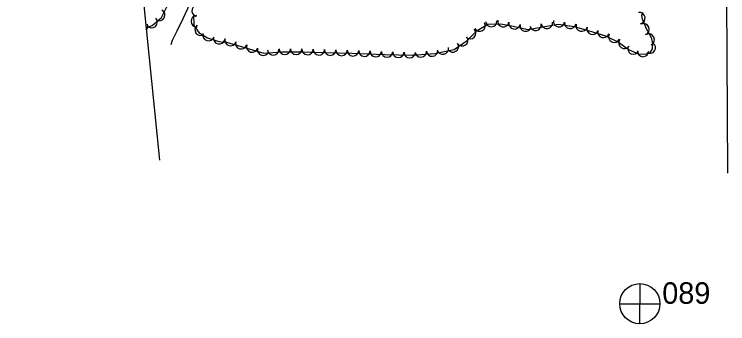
# Model space of a CAD drawing. Extents: x 296487 to 298842, y 31545 to 32791.
# Drawn here: x 297235.4 to 297732.5, y 31644.4 to 31860.3 of the extents above; entities that cross this region are included whole.
import ezdxf

# ---------------------------------------------------------------- set-up
doc = ezdxf.new("R2010")
doc.units = 0
for name, color, linetype in [('Level 11', 7, 'Continuous'), ('Level 17', 7, 'Continuous'), ('Level 18', 7, 'Continuous'), ('Level 4', 7, 'Continuous')]:
    doc.layers.add(name, color=color, linetype=linetype)

msp = doc.modelspace()

# ---------------------------------------------------------------- linework, layer by layer
at = {"layer": 'Level 11'}
msp.add_lwpolyline([(297732.45, 31749.54), (297732.24, 31791.84), (297732.13, 31829.29), (297731.83, 31872.75), (297730.81, 31924.68), (297730.53, 31968.01), (297729.53, 32021.42), (297729.12, 32084.97), (297728.52, 32147.82), (297727.87, 32212.59), (297727.19, 32277.97), (297726.38, 32352.97), (297725.93, 32414.91), (297724.99, 32486.15), (297724.55, 32554.59), (297723.53, 32621.52), (297723.38, 32689.57), (297722.58, 32747.62), (297722.25, 32760.6)], dxfattribs=at)
at = {"layer": 'Level 17'}
msp.add_lwpolyline([(297623.99, 32250.43), (297610.13, 32233.83), (297591.62, 32212.39), (297578.2, 32195.81), (297559.31, 32173.69), (297545.59, 32153.8), (297535.31, 32140.44), (297511.71, 32112.03), (297495.92, 32087.9), (297480.91, 32066.68), (297468.73, 32050.81), (297458.54, 32035.07), (297449.94, 32023.36), (297435.5, 32005.16), (297419.75, 31981.41), (297405.85, 31956.85), (297394.34, 31937.67), (297382.2, 31916.55), (297361.04, 31874.71), (297352.86, 31857.17), (297348.71, 31848.4), (297345.52, 31842.04), (297344.4, 31839.03)], dxfattribs=at)
at = {"layer": 'Level 18'}
for points in [[(297327.25, 31850.84), (297331.54, 31852.45), (297337.95, 31858.15), (297343.21, 31868.17), (297347.46, 31877.57), (297351.9, 31884.76), (297355.88, 31890.53), (297356.1, 31891.33), (297357.16, 31897.95)], [(297360.33, 31860.44), (297360.54, 31852.55), (297364.05, 31847.63), (297369.95, 31843.77), (297377.33, 31841.56), (297381.68, 31840.65)], [(297381.59, 31841.4), (297409.29, 31833.19), (297421.76, 31834.08), (297435.27, 31834.04), (297451.57, 31833.6), (297470.49, 31833.1), (297493.49, 31832.24), (297512.54, 31831.72), (297528.31, 31832.99), (297541.78, 31835.82), (297550.86, 31841.93), (297557.84, 31848.97), (297565.34, 31853.28), (297574.38, 31853.7), (297581.89, 31852.21), (297593.54, 31849.78), (297602.5, 31851.4), (297614.3, 31853.45), (297625.59, 31851.69), (297635.87, 31848.64), (297647.42, 31845.35), (297656.26, 31840.89), (297663.83, 31835.37), (297670.3, 31832.61), (297674.86, 31832.56), (297678.31, 31833.41), (297680.11, 31836.14), (297680.38, 31839.81), (297679.52, 31843.08), (297678.55, 31845.21), (297675.92, 31850.06), (297673.17, 31856.85), (297672.71, 31859.47), (297673.38, 31861.82)]]:
    msp.add_lwpolyline(points, dxfattribs=at)
for centre, radius, start, end in [((297363.15, 31862.68), 4.01, 74.2267, 254.2113), ((297336.41, 31859.7), 4, 242.3173, 62.3019), ((297362.56, 31855.41), 4.01, 91.5031, 271.4877), ((297670.94, 31857.62), 3.96, 279.9695, 99.9541), ((297331.08, 31854.84), 4, 221.6068, 41.5915), ((297559.64, 31852.39), 3.96, 209.8823, 29.867), ((297567.76, 31855.46), 3.96, 182.6945, 2.6792), ((297576.14, 31855.46), 3.96, 168.7931, 348.7777), ((297583.92, 31853.9), 3.96, 168.2529, 348.2376), ((297606.45, 31854.19), 3.96, 189.8481, 9.8328), ((297614.92, 31855.45), 3.96, 171.1845, 351.1691), ((297622.74, 31854.23), 3.96, 171.1845, 351.1691), ((297324.48, 31852.03), 4, 317.0734, 20.6017), ((297365.27, 31849.53), 4.01, 125.5751, 305.5598), ((297553.1, 31847.12), 3.96, 225.2202, 45.2049), ((297591.66, 31852.29), 3.96, 168.2529, 348.2376), ((297598.65, 31852.81), 3.96, 190.2207, 10.2054), ((297630.69, 31852.34), 3.96, 163.4559, 343.4405), ((297638.25, 31850.11), 3.96, 164.0996, 344.0843), ((297673.79, 31849.8), 3.96, 292.0009, 111.9856), ((297370.68, 31845.74), 4.01, 163.292, 343.2767), ((297378.19, 31843.52), 4.01, 168.2661, 348.2508), ((297547.51, 31842.17), 3.96, 213.9344, 33.9191), ((297645.86, 31847.94), 3.96, 164.0996, 344.0843), ((297653.44, 31844.63), 3.96, 153.2639, 333.2486), ((297677.43, 31842.68), 3.96, 294.5386, 114.5233), ((297385.97, 31842.26), 3.96, 163.5052, 343.4899), ((297393.55, 31840.01), 3.96, 163.5052, 343.4899), ((297540.94, 31837.76), 3.96, 213.9344, 33.9191), ((297660.48, 31840.38), 3.96, 143.9214, 323.9061), ((297678.2, 31837), 3.96, 236.5752, 56.5599), ((297401.14, 31837.77), 3.96, 163.5052, 343.4899), ((297408.72, 31835.52), 3.96, 163.5052, 343.4899), ((297415.83, 31835.73), 3.96, 184.0717, 4.0564), ((297423.88, 31836.14), 3.96, 179.838, 359.8227), ((297431.8, 31836.12), 3.96, 179.838, 359.8227), ((297439.75, 31835.99), 3.96, 178.4652, 358.4499), ((297447.66, 31835.77), 3.96, 178.4652, 358.4499), ((297455.57, 31835.57), 3.96, 178.5154, 358.5001), ((297463.48, 31835.36), 3.96, 178.5154, 358.5001), ((297471.41, 31835.14), 3.96, 177.8588, 357.8435), ((297479.31, 31834.85), 3.96, 177.8588, 357.8435), ((297487.22, 31834.55), 3.96, 177.8588, 357.8435), ((297495.11, 31834.27), 3.96, 178.4224, 358.407), ((297518.59, 31834.28), 3.96, 184.6227, 4.6074), ((297526.47, 31834.92), 3.96, 184.6227, 4.6074), ((297533.99, 31836.3), 3.96, 191.889, 11.8737), ((297666.72, 31836.39), 3.96, 156.8935, 336.8782), ((297673.46, 31834.65), 3.96, 179.3418, 359.3264), ((297503.01, 31834.05), 3.96, 178.4224, 358.407), ((297510.92, 31833.83), 3.96, 178.4224, 358.407)]:
    msp.add_arc(centre, radius, start, end, dxfattribs=at)
at = {"layer": 'Level 4'}
for p, q in [((297671.16, 31672.44), (297671.09, 31644.59)), ((297657.25, 31658.42), (297685.16, 31658.4))]:
    msp.add_line(p, q, dxfattribs=at)
msp.add_lwpolyline([(297235.43, 32760.04), (297336.59, 31758.44)], dxfattribs=at)
msp.add_circle((297671.21, 31658.42), 14, dxfattribs=at)

# ---------------------------------------------------------------- texts
msp.add_text('089', height=15, dxfattribs=at).set_placement((297686.86, 31658.35))

doc.saveas('drawing.dxf')
